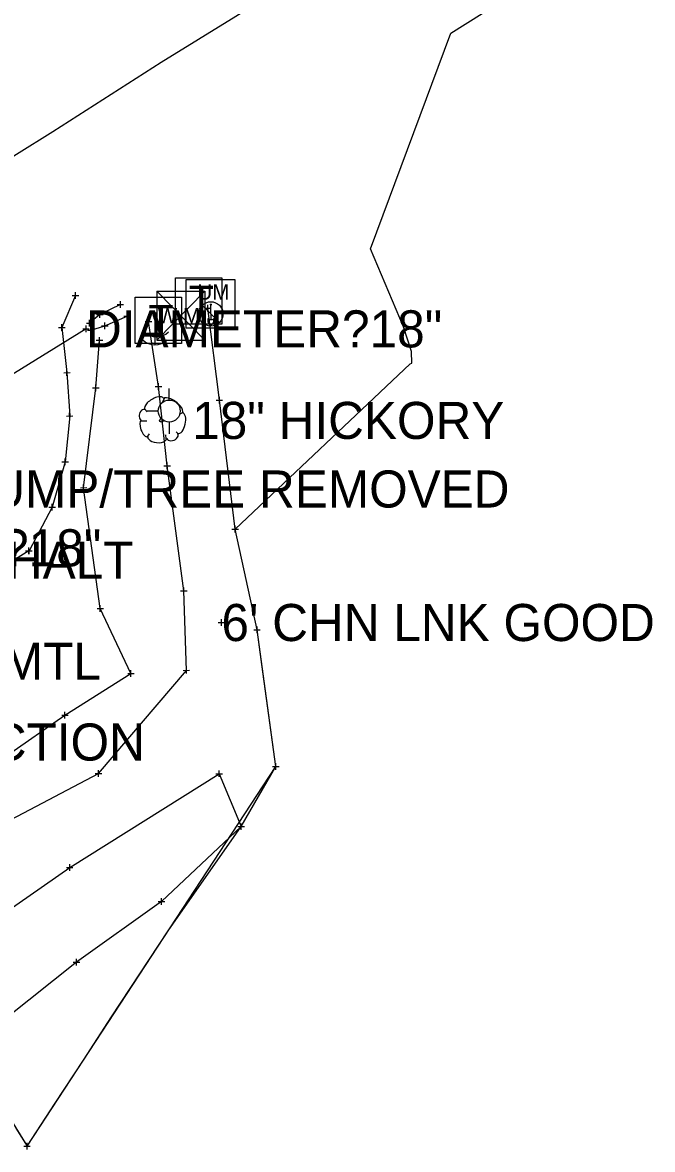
# Model space of a CAD drawing. Extents: x -1 to 1157254, y -1 to 2021979.
# Drawn here: x 1150902.4 to 1151024.8, y 2019855.4 to 2020074.3 of the extents above; entities that cross this region are included whole.
import ezdxf

# ---------------------------------------------------------------- set-up
doc = ezdxf.new("R2010")
doc.units = 0
for name, color, linetype in [('S_BUILDING_ANNOT', 7, 'Continuous'), ('S_CAL_CORNER', 7, 'Continuous'), ('S_CATCH_BASIN', 7, 'Continuous'), ('S_CATCH_BASIN_ANNOT', 7, 'Continuous'), ('S_CONTOUR_ANNOT', 7, 'Continuous'), ('S_CTL_TABLE', 7, 'Continuous'), ('S_CURB', 7, 'Continuous'), ('S_DRIVEWAY_ANNOT', 7, 'Continuous'), ('S_DROP_INLET_ANNOT', 7, 'Continuous'), ('S_EDGE_BITUMINOUS_ANNOT', 7, 'Continuous'), ('S_ENV_CONSTRAINT', 7, 'Continuous'), ('S_GAS_PUMP_ISLAND_ANNOT', 7, 'Continuous'), ('S_GATE', 7, 'Continuous'), ('S_GATE_ANNOT', 7, 'Continuous')]:
    doc.layers.add(name, color=color, linetype=linetype)

msp = doc.modelspace()

# ---------------------------------------------------------------- linework, layer by layer
at = {"layer": 'S_BUILDING_ANNOT'}
for p, q in [((1150912.09, 2020021.25), (1150913.36, 2020021.25)), ((1150912.73, 2020020.62), (1150912.72, 2020021.89)), ((1150912.72, 2020021.25), (1150912.72, 2020021.25)), ((1150921.44, 2020018.89), (1150921.44, 2020020.16)), ((1150917.44, 2020016.93), (1150917.44, 2020018.2)), ((1150920.8, 2020019.53), (1150922.07, 2020019.53)), ((1150921.44, 2020019.53), (1150921.44, 2020019.53)), ((1150914.83, 2020015.88), (1150916.1, 2020015.88)), ((1150915.47, 2020015.24), (1150915.47, 2020016.51)), ((1150915.47, 2020015.88), (1150915.47, 2020015.88)), ((1150916.8, 2020017.56), (1150918.07, 2020017.56)), ((1150917.44, 2020017.56), (1150917.44, 2020017.56)), ((1150918.44, 2020014.72), (1150918.44, 2020015.99)), ((1150922.1, 2020017.22), (1150923.37, 2020017.22)), ((1150922.74, 2020016.58), (1150922.74, 2020017.85)), ((1150922.74, 2020017.22), (1150922.74, 2020017.22)), ((1150909.41, 2020015.03), (1150910.69, 2020015.03)), ((1150910.05, 2020014.39), (1150910.05, 2020015.66)), ((1150910.05, 2020015.03), (1150910.05, 2020015.03)), ((1150914.13, 2020014.78), (1150915.41, 2020014.78)), ((1150914.77, 2020014.14), (1150914.77, 2020015.41)), ((1150914.77, 2020014.78), (1150914.77, 2020014.78)), ((1150915.03, 2020014.55), (1150916.3, 2020014.55)), ((1150915.67, 2020013.91), (1150915.67, 2020015.18)), ((1150915.67, 2020014.55), (1150915.67, 2020014.55)), ((1150917.8, 2020015.35), (1150919.08, 2020015.36)), ((1150918.44, 2020015.35), (1150918.44, 2020015.35)), ((1150910.43, 2020006.27), (1150911.7, 2020006.28)), ((1150911.07, 2020005.64), (1150911.07, 2020006.91)), ((1150911.07, 2020006.28), (1150911.07, 2020006.28)), ((1150911.59, 2019997.22), (1150911.58, 2019998.49)), ((1150910.95, 2019997.85), (1150912.22, 2019997.86)), ((1150911.59, 2019997.86), (1150911.59, 2019997.86)), ((1150910.72, 2019988.33), (1150910.72, 2019989.6)), ((1150910.09, 2019988.96), (1150911.36, 2019988.96)), ((1150910.72, 2019988.96), (1150910.72, 2019988.96)), ((1150908.18, 2019979.53), (1150908.17, 2019980.8)), ((1150907.54, 2019980.16), (1150908.81, 2019980.16)), ((1150908.18, 2019980.16), (1150908.18, 2019980.16)), ((1150903.69, 2019971.02), (1150903.68, 2019972.3)), ((1150903.05, 2019971.66), (1150904.32, 2019971.66)), ((1150903.69, 2019971.66), (1150903.69, 2019971.66)), ((1150940.44, 2019957.75), (1150941.72, 2019957.75)), ((1150941.08, 2019957.11), (1150941.08, 2019958.39)), ((1150941.08, 2019957.75), (1150941.08, 2019957.75))]:
    msp.add_line(p, q, dxfattribs=at)
at = {"layer": 'S_CAL_CORNER'}
for p, q in [((1150937.35, 2020019.35), (1150940.69, 2020016.02)), ((1150938.86, 2020019.58), (1150939.18, 2020019.58)), ((1150939.02, 2020017.69), (1150939.02, 2020019.42)), ((1150938.42, 2020016.78), (1150938.42, 2020016.6)), ((1150939.02, 2020017.69), (1150939.02, 2020016.63)), ((1150939.62, 2020016.79), (1150939.62, 2020016.56))]:
    msp.add_line(p, q, dxfattribs=at)
msp.add_lwpolyline([(1150934.26, 2020024.35), (1150943.67, 2020024.35), (1150943.67, 2020014.93), (1150934.26, 2020014.93)], close=True, dxfattribs=at)
msp.add_circle((1150939.02, 2020017.69), 2.36, dxfattribs=at)
for centre, radius, start, end in [((1150939.02, 2020019.58), 0.156, 180, 0), ((1150938.85, 2020017.18), 0.58, 223.1344, 287.472), ((1150939.19, 2020017.18), 0.58, 252.528, 316.8656)]:
    msp.add_arc(centre, radius, start, end, dxfattribs=at)
msp.add_ellipse((1150939.02, 2020016.44), major_axis=(0, -0.82), ratio=0.744362, start_param=4.519801, end_param=8.000179, dxfattribs=at)
at = {"layer": 'S_CATCH_BASIN'}
for p, q in [((1150928.36, 2020017.97), (1150928.36, 2020013.24)), ((1150928.11, 2020016.4), (1150928.11, 2020011.68)), ((1150930.94, 2020000.93), (1150930.94, 2020003.18)), ((1150928.84, 2019998.8), (1150926.52, 2019998.8)), ((1150931.01, 2019994.39), (1150931.01, 2019996.71))]:
    msp.add_line(p, q, dxfattribs=at)
msp.add_circle((1150930.94, 2019998.82), 2.13, dxfattribs=at)
for centre in [(1150928.43, 2020016.66), (1150928.17, 2020015.1)]:
    msp.add_arc(centre, 3.41, 226.3972, 313.6028, dxfattribs=at)
at = {"layer": 'S_CATCH_BASIN_ANNOT'}
for points in [[(1150932.16, 2020015.66), (1150932.16, 2020024.66), (1150941.16, 2020024.66), (1150941.16, 2020015.66)], [(1150924.32, 2020011.93), (1150924.32, 2020020.92), (1150933.32, 2020020.92), (1150933.32, 2020011.93)]]:
    msp.add_lwpolyline(points, close=True, dxfattribs=at)
at = {"layer": 'S_CONTOUR_ANNOT'}
for p, q in [((1150928.5, 2020022.08), (1150937.84, 2020022.08)), ((1150928.5, 2020022.08), (1150928.5, 2020012.59)), ((1150928.5, 2020022.08), (1150937.84, 2020012.59)), ((1150937.84, 2020022.08), (1150928.5, 2020012.59)), ((1150937.84, 2020022.08), (1150937.84, 2020012.59)), ((1150928.5, 2020012.59), (1150937.84, 2020012.59))]:
    msp.add_line(p, q, dxfattribs=at)
at = {"layer": 'S_CTL_TABLE'}
for p, q in [((1150937.82, 2020018.79), (1150939.09, 2020018.79)), ((1150938.46, 2020018.15), (1150938.46, 2020019.42)), ((1150938.46, 2020018.79), (1150938.46, 2020018.79)), ((1150926.28, 2020016.23), (1150927.56, 2020016.24)), ((1150926.92, 2020015.6), (1150926.92, 2020016.87)), ((1150926.92, 2020016.23), (1150926.92, 2020016.23)), ((1150916.76, 2020012.56), (1150918.03, 2020012.56)), ((1150917.4, 2020011.92), (1150917.4, 2020013.19)), ((1150917.4, 2020012.56), (1150917.4, 2020012.56)), ((1150916.02, 2020003.31), (1150917.29, 2020003.31)), ((1150916.65, 2020002.67), (1150916.65, 2020003.95)), ((1150916.65, 2020003.31), (1150916.65, 2020003.31)), ((1150928.23, 2020003.59), (1150929.5, 2020003.59)), ((1150928.86, 2020002.95), (1150928.86, 2020004.23)), ((1150928.86, 2020003.59), (1150928.86, 2020003.59)), ((1150940.04, 2020000.92), (1150941.32, 2020000.92)), ((1150940.68, 2020000.28), (1150940.68, 2020001.55)), ((1150940.68, 2020000.92), (1150940.68, 2020000.92)), ((1150929.92, 2019988.17), (1150931.2, 2019988.18)), ((1150930.56, 2019987.54), (1150930.56, 2019988.81)), ((1150930.56, 2019988.18), (1150930.56, 2019988.18)), ((1150913.67, 2019983.93), (1150914.94, 2019983.94)), ((1150914.3, 2019983.3), (1150914.3, 2019984.57)), ((1150914.3, 2019983.93), (1150914.3, 2019983.93)), ((1150943.77, 2019975.25), (1150943.77, 2019976.53)), ((1150943.13, 2019975.89), (1150944.41, 2019975.89)), ((1150943.77, 2019975.89), (1150943.77, 2019975.89)), ((1150903.63, 2019971.04), (1150903.63, 2019972.32)), ((1150902.99, 2019971.68), (1150904.27, 2019971.68)), ((1150903.63, 2019971.68), (1150903.63, 2019971.68)), ((1150933.13, 2019963.92), (1150934.4, 2019963.93)), ((1150933.76, 2019963.29), (1150933.76, 2019964.56)), ((1150933.76, 2019963.93), (1150933.76, 2019963.93)), ((1150917.54, 2019959.83), (1150917.54, 2019961.1)), ((1150916.91, 2019960.47), (1150918.18, 2019960.47)), ((1150917.54, 2019960.47), (1150917.54, 2019960.47)), ((1150948, 2019955.72), (1150948, 2019956.99)), ((1150947.36, 2019956.35), (1150948.63, 2019956.35)), ((1150948, 2019956.35), (1150948, 2019956.35)), ((1150923.49, 2019947.2), (1150923.49, 2019948.47)), ((1150933.63, 2019948.46), (1150934.9, 2019948.47)), ((1150934.27, 2019947.83), (1150934.27, 2019949.1)), ((1150934.27, 2019948.46), (1150934.27, 2019948.46)), ((1150922.86, 2019947.84), (1150924.13, 2019947.84)), ((1150923.49, 2019947.84), (1150923.49, 2019947.84)), ((1150910.05, 2019939.77), (1150911.32, 2019939.78)), ((1150910.68, 2019939.14), (1150910.68, 2019940.41)), ((1150910.68, 2019939.78), (1150910.68, 2019939.78)), ((1150951.63, 2019929.14), (1150951.63, 2019930.41)), ((1150916.54, 2019928.43), (1150917.81, 2019928.43)), ((1150917.18, 2019927.79), (1150917.18, 2019929.07)), ((1150917.18, 2019928.43), (1150917.18, 2019928.43)), ((1150940.01, 2019928.39), (1150941.28, 2019928.39)), ((1150940.64, 2019927.75), (1150940.64, 2019929.02)), ((1150940.64, 2019928.39), (1150940.64, 2019928.39)), ((1150951, 2019929.77), (1150952.27, 2019929.78)), ((1150951.63, 2019929.78), (1150951.63, 2019929.78)), ((1150944.28, 2019918.11), (1150945.55, 2019918.12)), ((1150944.91, 2019917.48), (1150944.91, 2019918.75)), ((1150944.91, 2019918.12), (1150944.91, 2019918.12)), ((1150911.59, 2019909.55), (1150911.59, 2019910.83)), ((1150910.95, 2019910.19), (1150912.22, 2019910.19)), ((1150911.59, 2019910.19), (1150911.59, 2019910.19)), ((1150929.45, 2019902.94), (1150929.45, 2019904.21)), ((1150928.81, 2019903.58), (1150930.09, 2019903.58)), ((1150929.45, 2019903.58), (1150929.45, 2019903.58)), ((1150912.3, 2019891.77), (1150913.57, 2019891.77)), ((1150912.94, 2019891.13), (1150912.93, 2019892.41)), ((1150912.94, 2019891.77), (1150912.94, 2019891.77)), ((1150902.66, 2019856.05), (1150903.93, 2019856.05)), ((1150903.3, 2019855.42), (1150903.3, 2019856.69)), ((1150903.3, 2019856.05), (1150903.3, 2019856.05))]:
    msp.add_line(p, q, dxfattribs=at)
at = {"layer": 'S_CURB'}
for p, q in [((1150929.94, 2020001.24), (1150929.56, 2020000.39)), ((1150926.15, 2019999.23), (1150926.65, 2019998.65)), ((1150933.51, 2019998.45), (1150932.85, 2019998.18)), ((1150925.49, 2019996.9), (1150926.61, 2019996.9)), ((1150926.65, 2019993.73), (1150927.12, 2019994.42)), ((1150930.33, 2019993.45), (1150930.25, 2019994.23)), ((1150932.73, 2019994.35), (1150932.27, 2019994.77))]:
    msp.add_line(p, q, dxfattribs=at)
msp.add_circle((1150929.39, 2019997), 0.34, dxfattribs=at)
for centre, major_axis, ratio, start_param, end_param in [((1150928.05, 2020000.2), (1.86, 1.08), 0.471018, 0, 3.141593), ((1150931.7, 2019999.87), (-1.81, 1.36), 0.405113, 3.141593, 6.283186), ((1150925.82, 2019998.08), (0.31, 1.03), 0.646762, 0, 3.141593), ((1150933.06, 2019996.47), (0.46, 2.04), 0.482994, 3.141593, 6.283185), ((1150926.12, 2019995.43), (-0.61, 1.6), 0.420543, 6.283185, 9.424777), ((1150928.58, 2019993.65), (-1.83, 0.19), 0.529943, 0, 3.141593), ((1150931.54, 2019993.95), (1.09, 0.46), 0.711534, 3.141592, 6.283185)]:
    msp.add_ellipse(centre, major_axis=major_axis, ratio=ratio, start_param=start_param, end_param=end_param, dxfattribs=at)
at = {"layer": 'S_DRIVEWAY_ANNOT'}
for points in [[(1150921.44, 2020019.53), (1150917.44, 2020017.56), (1150915.47, 2020015.88)], [(1150915.67, 2020014.55), (1150918.44, 2020015.35), (1150922.74, 2020017.22)]]:
    msp.add_lwpolyline(points, dxfattribs=at)
at = {"layer": 'S_DROP_INLET_ANNOT'}
msp.add_lwpolyline([(1150914.77, 2020014.78), (1150893.69, 2020001.75)], dxfattribs=at)
at = {"layer": 'S_EDGE_BITUMINOUS_ANNOT'}
for points in [[(1150903.3, 2019856.05), (1150951.63, 2019929.78), (1150948, 2019956.35), (1150943.77, 2019975.89), (1150940.68, 2020000.92), (1150938.46, 2020018.79)], [(1150850.71, 2019934.87), (1150861.27, 2019908.8), (1150891.69, 2019915), (1150917.18, 2019928.43), (1150934.27, 2019948.46), (1150933.76, 2019963.93), (1150930.56, 2019988.18), (1150928.86, 2020003.59), (1150926.92, 2020016.23)], [(1150859.74, 2019938.05), (1150874.27, 2019917.53), (1150887.9, 2019923.96), (1150910.68, 2019939.78), (1150923.49, 2019947.84), (1150917.54, 2019960.47), (1150914.3, 2019983.93), (1150916.65, 2020003.31), (1150917.4, 2020012.56)], [(1150903.63, 2019971.68), (1150893.08, 2019965.14), (1150871.28, 2019952.03), (1150860.51, 2019943.79)], [(1150839.31, 2019929.4), (1150845.25, 2019903.36), (1150846.63, 2019887.86), (1150855.84, 2019878.75), (1150869.72, 2019884.35), (1150882.93, 2019891.25), (1150896.11, 2019899.45), (1150911.59, 2019910.19), (1150940.64, 2019928.39), (1150944.91, 2019918.12), (1150929.45, 2019903.58), (1150912.94, 2019891.77), (1150899.18, 2019880.84), (1150890.57, 2019876.55), (1150903.3, 2019856.05)]]:
    msp.add_lwpolyline(points, dxfattribs=at)
at = {"layer": 'S_ENV_CONSTRAINT'}
msp.add_lwpolyline([(1150912.72, 2020021.25), (1150910.05, 2020015.03), (1150911.07, 2020006.28), (1150911.59, 2019997.86), (1150910.72, 2019988.96), (1150908.18, 2019980.16), (1150903.69, 2019971.66)], dxfattribs=at)
at = {"layer": 'S_GAS_PUMP_ISLAND_ANNOT'}
for points in [[(1150951.14, 2020079.99), (1150929.38, 2020066.49), (1150908.3, 2020053.04), (1150887.06, 2020039.85), (1150855.79, 2020029.67), (1150847.18, 2020024.57), (1150838.58, 2020019.48), (1150831.35, 2020015.2), (1150789.87, 2020023.58), (1150780.18, 2020046.65), (1150769.01, 2020065.16), (1150760.84, 2020080.67)], [(1150901.12, 2019859.56), (1150903.3, 2019856.05), (1150908.78, 2019864.41), (1150914.26, 2019872.78), (1150919.75, 2019881.14), (1150925.23, 2019889.5), (1150930.71, 2019897.87), (1150944.91, 2019918.12), (1150951.63, 2019929.78), (1150950.28, 2019939.68), (1150948.92, 2019949.59), (1150948, 2019956.35), (1150945.88, 2019966.12), (1150943.77, 2019975.89), (1150977.77, 2020007.99), (1150978.06, 2020008.12), (1150978.01, 2020010.38), (1150976.43, 2020015.16), (1150970.02, 2020030.31), (1150985.66, 2020072.23), (1150998.36, 2020080.24)]]:
    msp.add_lwpolyline(points, dxfattribs=at)

# ---------------------------------------------------------------- texts
at = {"layer": 'S_BUILDING_ANNOT'}
for p in [(1150914.77, 2020011.18), (1150848.52, 2019968.66)]:
    msp.add_text('DIAMETER?18"', height=7.2, dxfattribs=at).set_placement(p)
at = {"layer": 'S_CAL_CORNER'}
msp.add_text('UM', height=2.999, dxfattribs=at).set_placement((1150936.4, 2020020.46))
at = {"layer": 'S_CATCH_BASIN_ANNOT'}
for p in [(1150934.73, 2020017.16), (1150926.89, 2020013.43)]:
    msp.add_text('T', height=6, dxfattribs=at).set_placement(p)
at = {"layer": 'S_CONTOUR_ANNOT'}
msp.add_text('W M', height=2.999, dxfattribs=at).set_placement((1150928.71, 2020015.85))
at = {"layer": 'S_GATE'}
for s, p in [('STUMP/TREE REMOVED', (1150883.66, 2019980.08)), ('ASPHALT', (1150880.12, 2019966.27)), ("6' CHN LNK GOOD", (1150941.08, 2019954.15)), ('1-S-MTL', (1150880.21, 2019946.62)), ('UNDER CONSTRUCTION', (1150811.74, 2019930.94))]:
    msp.add_text(s, height=7.2, dxfattribs=at).set_placement(p)
at = {"layer": 'S_GATE_ANNOT'}
msp.add_text('18" HICKORY', height=7.2, dxfattribs=at).set_placement((1150935.39, 2019993.4))

doc.saveas('drawing.dxf')
